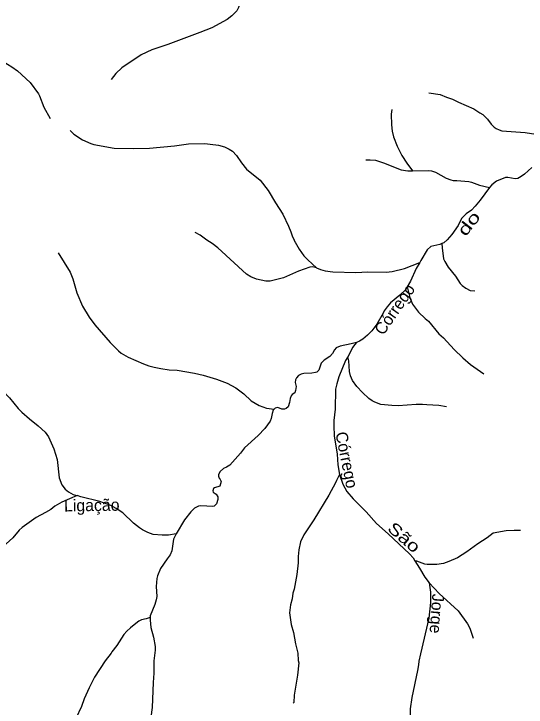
# Model space of a CAD drawing. Extents: x 551.6 to 577.6, y 7567 to 7594.7.
# Drawn here: x 568.58 to 572.91, y 7584.89 to 7590.74 of the extents above; entities that cross this region are included whole.
import ezdxf
from ezdxf.enums import TextEntityAlignment as Align

# ---------------------------------------------------------------- set-up
doc = ezdxf.new("R2010")
doc.units = 0
doc.header["$LTSCALE"] = 0.04
doc.layers.add('61', color=7, linetype='Continuous')
doc.layers.add('7', color=7, linetype='Continuous', lineweight=25)

msp = doc.modelspace()

# ---------------------------------------------------------------- linework, layer by layer
at = {"layer": '7'}
for points in [[(570.6518, 7591.2953), (570.622, 7591.2686), (570.5737, 7591.1929), (570.5616, 7591.1688), (570.531, 7591.0819), (570.5214, 7591.0432), (570.5149, 7590.9885), (570.5158, 7590.9708), (570.5005, 7590.8871), (570.498, 7590.8436), (570.4828, 7590.7945), (570.4683, 7590.7672), (570.4264, 7590.7253), (570.3862, 7590.6947), (570.2574, 7590.6247), (570.156, 7590.5837)], [(568.115, 7590.9796), (568.2333, 7590.7801), (568.3653, 7590.5764), (568.3879, 7590.533), (568.4257, 7590.4332), (568.4514, 7590.3833), (568.4949, 7590.3382), (568.5673, 7590.2939), (568.614, 7590.2601), (568.7235, 7590.162)], [(570.156, 7590.5837), (569.884, 7590.4831), (569.7488, 7590.438), (569.6595, 7590.3945), (569.4977, 7590.2859), (569.4453, 7590.2384), (569.4076, 7590.1877)], [(568.7235, 7590.162), (568.7919, 7590.0678), (568.8023, 7590.0485), (568.8377, 7589.9551), (568.8917, 7589.8594)], [(572.0883, 7590.0759), (572.1841, 7590.0597), (572.2372, 7590.0372), (572.2887, 7590.0219), (572.3403, 7589.9962), (572.469, 7589.9406), (572.5189, 7589.906), (572.5455, 7589.8916), (572.5842, 7589.8514), (572.6155, 7589.8111), (572.6396, 7589.7861), (572.6565, 7589.7732), (572.6815, 7589.7612), (572.704, 7589.7547), (572.902, 7589.7394), (572.9921, 7589.7266), (573.0662, 7589.7121)], [(571.7769, 7589.935), (571.772, 7589.8956), (571.7729, 7589.8054), (571.7785, 7589.7507), (571.7906, 7589.7024), (571.8203, 7589.6236), (571.8614, 7589.5463), (571.904, 7589.4803), (571.9514, 7589.4173)], [(569.0607, 7589.7563), (569.0905, 7589.7266), (569.1645, 7589.6767), (569.2353, 7589.6469), (569.2611, 7589.638), (569.4317, 7589.6091), (569.5911, 7589.6058), (569.7311, 7589.6074), (569.9419, 7589.626), (570.0595, 7589.6445), (570.1979, 7589.6461), (570.2429, 7589.642)], [(570.2429, 7589.642), (570.3122, 7589.6324), (570.3637, 7589.6179), (570.4039, 7589.5994), (570.4297, 7589.5817), (570.465, 7589.5463), (570.5061, 7589.4835), (570.5496, 7589.4296), (570.6646, 7589.3371), (570.733, 7589.2501), (570.7934, 7589.1455), (570.8562, 7589.0505), (570.9045, 7588.9491), (570.9238, 7588.9025), (570.9334, 7588.8687), (570.9527, 7588.8308), (570.9527, 7588.8252), (570.956, 7588.8236), (570.956, 7588.8179), (570.9608, 7588.8139), (570.9938, 7588.756), (571.0332, 7588.6997), (571.0662, 7588.6642), (571.1407, 7588.5977)], [(571.5572, 7589.5093), (571.5934, 7589.5101), (571.6385, 7589.506), (571.7053, 7589.4851), (571.8542, 7589.4256), (571.9105, 7589.4175), (571.9514, 7589.4173)], [(572.9581, 7589.4442), (572.8964, 7589.3869), (572.8698, 7589.3676), (572.8392, 7589.3523), (572.8183, 7589.3483), (572.7555, 7589.3588), (572.7362, 7589.3588), (572.6589, 7589.329), (572.6203, 7589.2992), (572.6012, 7589.2752)], [(571.9514, 7589.4173), (572.0875, 7589.4191), (572.1101, 7589.4159), (572.1439, 7589.4062), (572.234, 7589.3555), (572.2759, 7589.3394), (572.2952, 7589.3354), (572.3258, 7589.3354), (572.4256, 7589.3258), (572.4481, 7589.3201), (572.5157, 7589.2944), (572.6012, 7589.2752)], [(572.6012, 7589.2752), (572.5221, 7589.1672), (572.4795, 7589.1165), (572.4481, 7589.0843), (572.4038, 7589.0538), (572.3644, 7589.0127), (572.3362, 7588.9556), (572.2823, 7588.8775)], [(571.1407, 7588.5977), (571.1073, 7588.6055), (571.0848, 7588.6039), (570.989, 7588.5676), (570.861, 7588.5113), (570.75, 7588.4839), (570.7129, 7588.4839), (570.6341, 7588.5008), (570.5866, 7588.5218), (570.5496, 7588.5443), (570.3073, 7588.7648), (570.2582, 7588.8035), (570.214, 7588.8308), (570.1576, 7588.8735), (570.115, 7588.8968)], [(572.2823, 7588.8775), (572.2429, 7588.8324), (572.2147, 7588.8091), (572.199, 7588.8024)], [(572.199, 7588.8024), (572.1825, 7588.7954), (572.1069, 7588.7769), (572.0754, 7588.7503), (572.0199, 7588.6594), (572.0134, 7588.6421)], [(572.199, 7588.8024), (572.2002, 7588.7656), (572.2139, 7588.6739), (572.2227, 7588.6514), (572.2509, 7588.6039), (572.3129, 7588.5274), (572.3547, 7588.4646), (572.37, 7588.4477), (572.4014, 7588.4252), (572.4376, 7588.4067), (572.4763, 7588.4019)], [(568.9577, 7588.7246), (569.0599, 7588.5596), (569.0824, 7588.5033), (569.117, 7588.3874), (569.1645, 7588.2747), (569.22, 7588.1798), (569.2691, 7588.1154), (569.3987, 7587.9673), (569.4671, 7587.8965), (569.492, 7587.8771), (569.5492, 7587.8441), (569.678, 7587.787), (569.723, 7587.7709), (569.7681, 7587.7596)], [(571.1407, 7588.5977), (571.1749, 7588.5837), (571.2135, 7588.5725), (571.2779, 7588.5636), (571.4711, 7588.5588), (571.5741, 7588.5636), (571.7286, 7588.5612), (571.7801, 7588.566), (571.8831, 7588.5902), (572.0134, 7588.6421)], [(572.0134, 7588.6421), (571.9813, 7588.5918), (571.9338, 7588.484), (571.9044, 7588.4362)], [(571.9044, 7588.4362), (571.896, 7588.418), (571.8445, 7588.3672), (571.7656, 7588.3013), (571.7374, 7588.2691), (571.7117, 7588.2345), (571.7036, 7588.2152), (571.6497, 7588.1218), (571.6079, 7588.0663), (571.5708, 7588.0276), (571.5322, 7587.9954)], [(571.9044, 7588.4362), (571.9274, 7588.3455), (571.9507, 7588.2892), (572.0006, 7588.2216), (572.0578, 7588.1685), (572.0859, 7588.1467), (572.1728, 7588.0397), (572.2115, 7588.0059), (572.304, 7587.9061), (572.3749, 7587.8361), (572.4392, 7587.7822), (572.5535, 7587.7033)], [(571.4791, 7587.9673), (571.434, 7587.9544), (571.3391, 7587.9367), (571.3053, 7587.9206), (571.2924, 7587.9045), (571.2755, 7587.8739), (571.2514, 7587.8473), (571.2039, 7587.816), (571.1805, 7587.7918), (571.1588, 7587.7323), (571.1419, 7587.717), (571.1331, 7587.7121), (571.1009, 7587.7065), (571.0333, 7587.7049), (571.0107, 7587.7001), (570.9882, 7587.6872), (570.9713, 7587.6695), (570.9624, 7587.6502), (570.9608, 7587.6277), (570.9672, 7587.5939), (570.964, 7587.5601), (570.9576, 7587.5415), (570.9351, 7587.527), (570.927, 7587.515), (570.9173, 7587.4925), (570.9109, 7587.4587)], [(571.4791, 7587.9673), (571.4598, 7587.9464), (571.4469, 7587.927), (571.405, 7587.8451)], [(571.5322, 7587.9954), (571.5041, 7587.9777), (571.4791, 7587.9673)], [(571.405, 7587.8451), (571.3857, 7587.8144), (571.3286, 7587.6776), (571.3109, 7587.618), (571.3012, 7587.5729), (571.2972, 7587.4039), (571.2867, 7587.309), (571.2867, 7587.2639), (571.2892, 7587.177), (571.3141, 7587.0224)], [(572.238, 7587.4224), (572.1745, 7587.4345), (572.0731, 7587.4393), (572.0344, 7587.4441), (571.9829, 7587.4433), (571.8284, 7587.4321), (571.7769, 7587.4337), (571.6835, 7587.4441), (571.632, 7587.4618), (571.6095, 7587.4739), (571.5829, 7587.494), (571.5282, 7587.5447), (571.4807, 7587.5939), (571.4429, 7587.6454), (571.426, 7587.684), (571.4195, 7587.7226), (571.4123, 7587.8128), (571.405, 7587.8451)], [(569.7681, 7587.7596), (569.8244, 7587.7468), (569.8969, 7587.7371), (569.9645, 7587.7323), (570.111, 7587.7073), (570.1834, 7587.6904), (570.2961, 7587.6582), (570.3862, 7587.6236), (570.4586, 7587.5842), (570.5278, 7587.5327), (570.5874, 7587.4747), (570.6566, 7587.4345), (570.7178, 7587.4128), (570.7815, 7587.4033)], [(568.3989, 7587.6606), (568.4247, 7587.626), (568.5488, 7587.5005), (568.6196, 7587.4104), (568.6518, 7587.3774), (568.7162, 7587.321), (568.7911, 7587.2615)], [(570.9109, 7587.4587), (570.8996, 7587.424), (570.8844, 7587.4095), (570.8707, 7587.4047), (570.8482, 7587.4047), (570.8144, 7587.4184), (570.791, 7587.4128), (570.7815, 7587.4033)], [(570.7815, 7587.4033), (570.7741, 7587.3959), (570.7644, 7587.3669), (570.7572, 7587.3251), (570.7475, 7587.3025), (570.7049, 7587.2413), (570.647, 7587.1818), (570.5318, 7587.0764), (570.4997, 7587.0313), (570.4071, 7586.9307), (570.3814, 7586.9146), (570.3548, 7586.9033), (570.3274, 7586.8776), (570.3137, 7586.8526), (570.3129, 7586.839), (570.317, 7586.8204), (570.3202, 7586.8196), (570.329, 7586.8027)], [(568.7911, 7587.2615), (568.8498, 7587.2084), (568.8772, 7587.1705), (568.9231, 7587.0675), (568.9496, 7586.9774), (568.9681, 7586.8245), (568.9907, 7586.7649), (569.018, 7586.7287), (569.0454, 7586.7045), (569.084, 7586.682), (569.1181, 7586.6756)], [(571.3141, 7587.0224), (571.3189, 7586.9339), (571.3341, 7586.8525)], [(570.329, 7586.8027), (570.3339, 7586.7923), (570.3242, 7586.7544), (570.2775, 7586.7391), (570.2695, 7586.7327), (570.2655, 7586.715), (570.2663, 7586.7037), (570.292, 7586.6852), (570.3057, 7586.6635), (570.3057, 7586.641), (570.2944, 7586.6031), (570.2751, 7586.5854), (570.2655, 7586.5822), (570.1641, 7586.587), (570.1447, 7586.5854), (570.1093, 7586.5677), (570.0779, 7586.5372), (570.0248, 7586.4704), (569.9562, 7586.3512)], [(571.3341, 7586.8525), (571.3085, 7586.8019), (571.3012, 7586.781), (571.2449, 7586.678), (571.1169, 7586.4704), (571.0324, 7586.3416), (571.0059, 7586.282), (570.9914, 7586.2144), (570.9866, 7586.1581), (570.9866, 7586.105), (570.9753, 7586.0068), (570.9511, 7585.8829), (570.9415, 7585.8491), (570.9351, 7585.8008)], [(571.3341, 7586.8525), (571.3624, 7586.7714), (571.397, 7586.707), (571.4485, 7586.6458), (571.5596, 7586.5364), (571.6481, 7586.4373), (571.7455, 7586.3504), (571.9258, 7586.1806)], [(569.1181, 7586.6756), (568.9891, 7586.6192), (568.9319, 7586.5838), (568.8957, 7586.5564), (568.8523, 7586.5323)], [(569.9562, 7586.3512), (569.8904, 7586.3408), (569.8357, 7586.34), (569.7601, 7586.3464), (569.715, 7586.3633), (569.6699, 7586.3858), (569.6466, 7586.4011), (569.5959, 7586.4414), (569.5041, 7586.5275), (569.4494, 7586.5645), (569.4043, 7586.5902), (569.311, 7586.6232), (569.1499, 7586.6638), (569.1181, 7586.6756)], [(568.8523, 7586.5323), (568.7734, 7586.4888), (568.6551, 7586.4035), (568.6285, 7586.381), (568.5762, 7586.3182), (568.5207, 7586.2675), (568.4788, 7586.2353), (568.4193, 7586.1975), (568.3919, 7586.183), (568.1698, 7586.0881), (567.9557, 7586.0084), (567.8945, 7585.9907)], [(569.9562, 7586.3512), (569.9339, 7586.3046), (569.9194, 7586.208), (569.9041, 7586.1742), (569.8783, 7586.1388)], [(572.8626, 7586.3786), (572.8103, 7586.3802), (572.7427, 7586.3754), (572.6332, 7586.3577), (572.5801, 7586.3182), (572.5028, 7586.2675), (572.4095, 7586.1975), (572.3306, 7586.1492), (572.259, 7586.1162), (572.2115, 7586.1001), (572.1568, 7586.0913), (572.1004, 7586.0905)], [(571.9258, 7586.1806), (571.9551, 7586.148), (571.9691, 7586.1215)], [(569.8783, 7586.1388), (569.8228, 7586.0567), (569.7987, 7585.9971), (569.7922, 7585.9746), (569.785, 7585.907), (569.7906, 7585.8217), (569.7858, 7585.7927), (569.7761, 7585.7541), (569.7359, 7585.6591), (569.7353, 7585.6446)], [(571.9691, 7586.1215), (572.0111, 7586.0615), (572.0561, 7585.9843), (572.0914, 7585.9356)], [(572.1004, 7586.0905), (572.0747, 7586.0905), (572.0554, 7586.0945), (571.9878, 7586.1186), (571.9691, 7586.1215)], [(572.0914, 7585.9356), (572.102, 7585.8571), (572.1028, 7585.7702), (572.0875, 7585.6398), (572.0175, 7585.3388), (572.0038, 7585.2744), (572.0022, 7585.2455), (571.9926, 7585.1972)], [(572.0914, 7585.9356), (572.1761, 7585.8458), (572.3354, 7585.6994), (572.4143, 7585.5899), (572.4352, 7585.5545), (572.4642, 7585.47)], [(570.9351, 7585.8008), (570.9206, 7585.7525), (570.9133, 7585.6849), (570.927, 7585.5851), (570.9463, 7585.5175), (570.964, 7585.4209), (570.9833, 7585.342), (570.9866, 7585.2809), (570.9914, 7585.2615), (570.9793, 7585.1569), (570.9503, 7584.9895), (570.9479, 7584.9267), (570.9423, 7584.9195)], [(569.7353, 7585.6446), (569.7024, 7585.6322), (569.6619, 7585.6245), (569.6401, 7585.6124), (569.6136, 7585.5947), (569.5701, 7585.5577), (569.5395, 7585.5287), (569.5146, 7585.4998), (569.4534, 7585.408), (569.4116, 7585.3533), (569.4075, 7585.3436), (569.3568, 7585.2793), (569.2667, 7585.1416), (569.2192, 7585.0491), (569.179, 7584.9573)], [(569.7353, 7585.6446), (569.7343, 7585.6221), (569.7407, 7585.5593), (569.7649, 7585.4788), (569.7778, 7585.4), (569.7778, 7585.3686), (569.7665, 7585.2776), (569.7665, 7585.1746), (569.7609, 7585.0958)], [(571.9926, 7585.1972), (571.9443, 7584.9686), (571.9306, 7584.8736), (571.929, 7584.7256), (571.9547, 7584.5501), (571.9676, 7584.4873), (571.9861, 7584.4479), (571.9893, 7584.4326), (572.0264, 7584.3441), (572.0738, 7584.2547), (572.0964, 7584.2129)], [(569.7609, 7585.0958), (569.7528, 7584.8849), (569.7303, 7584.7207), (569.7246, 7584.6612), (569.7246, 7584.6274), (569.7182, 7584.5823), (569.723, 7584.5147), (569.7335, 7584.4761), (569.7496, 7584.4471), (569.7673, 7584.4237), (569.9162, 7584.2749), (569.9435, 7584.2411), (569.9653, 7584.1928), (569.9693, 7584.1735), (569.9717, 7584.1541), (569.9661, 7584.0898), (569.9741, 7584.0447), (569.9933, 7583.9944)], [(569.179, 7584.9573), (569.1548, 7584.8929), (569.1082, 7584.7915), (569.0631, 7584.6402), (569.0599, 7584.6032), (569.0486, 7584.5485), (569.0293, 7584.5034), (569.0027, 7584.4278), (568.9689, 7584.3087), (568.9488, 7584.258)]]:
    msp.add_lwpolyline(points, dxfattribs=at)

# ---------------------------------------------------------------- texts
at = {"layer": '61'}
for s, rotation, width, p in [('do', 52.154, 1.45, (572.4655, 7588.9408)), ('São', 318.895, 1.3, (571.8471, 7586.2834))]:
    msp.add_text(s, height=0.1, rotation=rotation, dxfattribs=dict(at, width=width)).set_placement(p, align=Align.CENTER)
for s, rotation, p in [('Córrego', 55.247, (571.8408, 7588.2189)), ('Córrego', 281.464, (571.3469, 7586.9651)), ('Ligação', 0.903, (569.2433, 7586.5427)), ('Jorge', 265.861, (572.1069, 7585.6797))]:
    msp.add_text(s, height=0.1, rotation=rotation, dxfattribs=at).set_placement(p, align=Align.CENTER)

doc.saveas('drawing.dxf')
